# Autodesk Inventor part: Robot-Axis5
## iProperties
Shininess: 21.0
Length Units: 11269
Angle Units: 11279
Time Units: 11290
Mass Units: 11283
Length Display Precision: 3
Angle Display Precision: 2
Created: 2001-08
Part Number: Robot-Axis5
Document SubType Name: ﾓﾃﾞﾘﾝｸﾞ
Designer: Administrator
Density: 1 g/cm^3
Density: 0.0
Volumn: 0.0
Area: 0.0
PropertySet Name: Model Information
Control State: 0
Master: False
Checked Out: False
Author: Administrator
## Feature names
1. 押し出し1 [Extrusion]
2. 押し出し2 [Extrusion]
3. Mirror1
4. 押し出し3 [Extrusion]
5. Shell1
6. Hole1
7. Hole2
